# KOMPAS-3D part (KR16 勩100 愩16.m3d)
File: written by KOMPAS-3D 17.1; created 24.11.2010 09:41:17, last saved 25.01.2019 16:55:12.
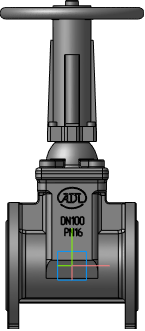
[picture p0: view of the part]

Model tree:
1. Плоскость XY
2. Плоскость ZX
3. Плоскость ZY
4. Ось X
5. Ось Y
6. Ось Z
7. Начало координат
8. Операция без истории:2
